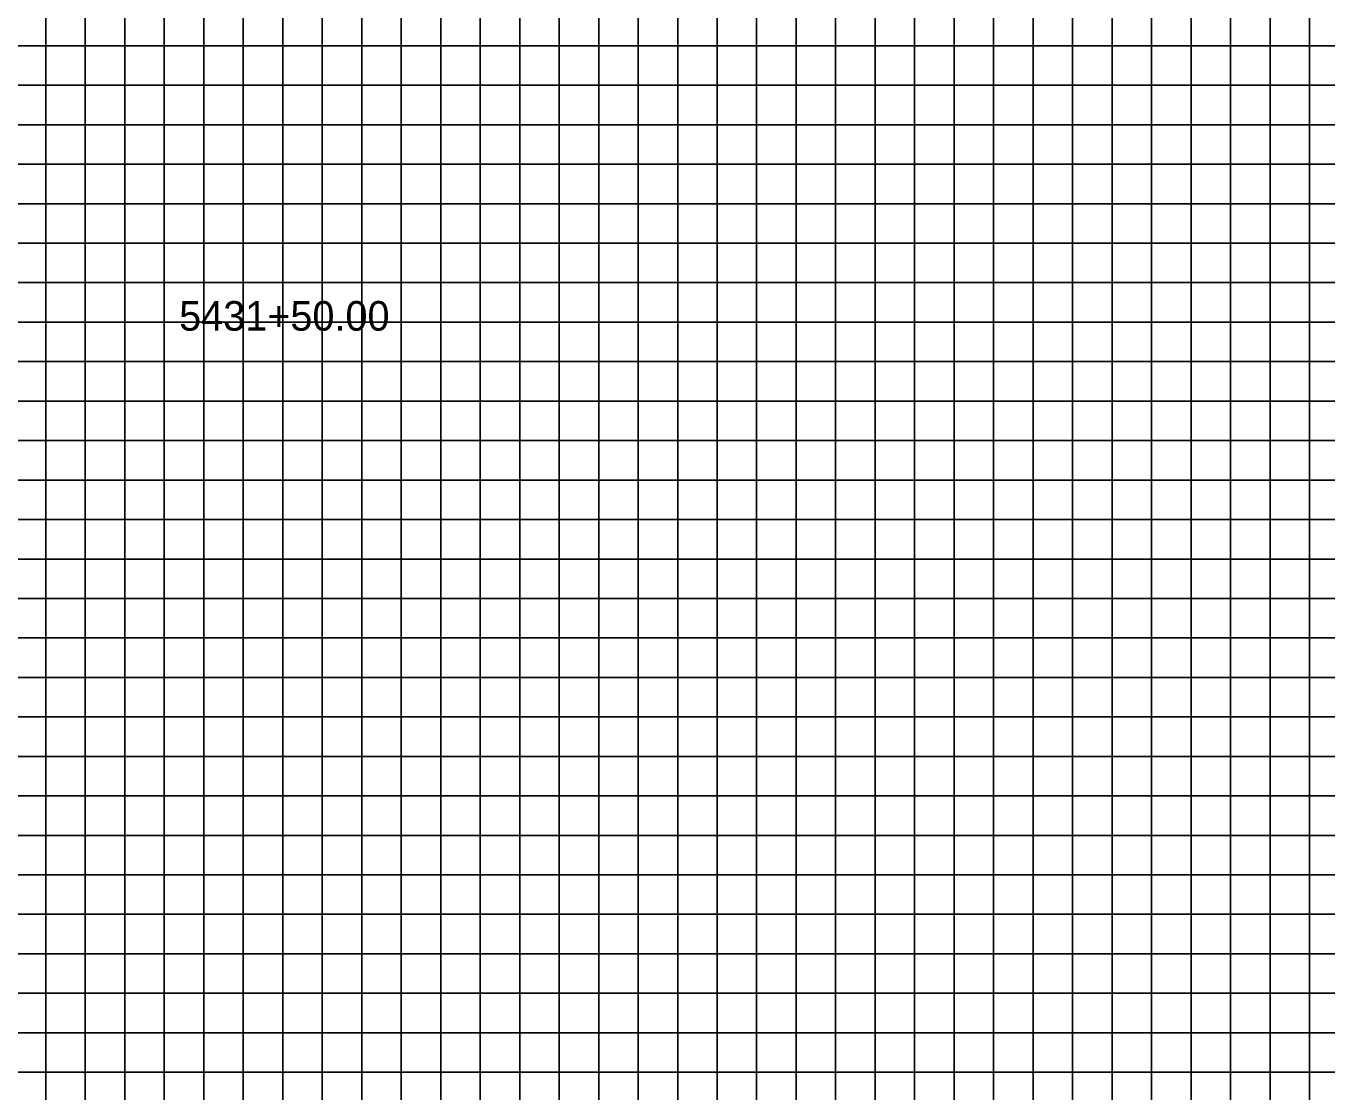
# Model space of a CAD drawing. Extents: x 967 to 1326, y 964 to 3144.
# Drawn here: x 1147 to 1212.9, y 2699 to 2753 of the extents above; entities that cross this region are included whole.
import ezdxf

# ---------------------------------------------------------------- set-up
doc = ezdxf.new("R2010")
doc.units = 0
for name, color, linetype in [('Default', 7, 'Continuous'), ('RD_GPK_XS_Cell', 7, 'Continuous'), ('RD_XS_ExGround', 7, 'Continuous')]:
    doc.layers.add(name, color=color, linetype=linetype)

msp = doc.modelspace()

# ---------------------------------------------------------------- linework, layer by layer
at = {"layer": 'RD_GPK_XS_Cell'}
for p, q in [((1150, 2680), (1150, 2850)), ((1160, 2680), (1160, 2850)), ((1170, 2680), (1170, 2850)), ((1180, 2680), (1180, 2850)), ((1190, 2680), (1190, 2850)), ((1200, 2680), (1200, 2850)), ((1210, 2680), (1210, 2850)), ((1000, 2750), (1320, 2750)), ((1000, 2740), (1320, 2740)), ((1000, 2730), (1320, 2730)), ((1000, 2720), (1320, 2720)), ((1000, 2710), (1320, 2710)), ((1000, 2700), (1320, 2700))]:
    msp.add_line(p, q, dxfattribs=at)
at = {"layer": 'RD_XS_ExGround'}
for p, q in [((1148, 2680), (1148, 2850)), ((1152, 2680), (1152, 2850)), ((1154, 2680), (1154, 2850)), ((1156, 2680), (1156, 2850)), ((1158, 2680), (1158, 2850)), ((1162, 2680), (1162, 2850)), ((1164, 2680), (1164, 2850)), ((1166, 2680), (1166, 2850)), ((1168, 2680), (1168, 2850)), ((1172, 2680), (1172, 2850)), ((1174, 2680), (1174, 2850)), ((1176, 2680), (1176, 2850)), ((1178, 2680), (1178, 2850)), ((1182, 2680), (1182, 2850)), ((1184, 2680), (1184, 2850)), ((1186, 2680), (1186, 2850)), ((1188, 2680), (1188, 2850)), ((1192, 2680), (1192, 2850)), ((1194, 2680), (1194, 2850)), ((1196, 2680), (1196, 2850)), ((1198, 2680), (1198, 2850)), ((1202, 2680), (1202, 2850)), ((1204, 2680), (1204, 2850)), ((1206, 2680), (1206, 2850)), ((1208, 2680), (1208, 2850)), ((1212, 2680), (1212, 2850)), ((1000, 2752), (1320, 2752)), ((1000, 2748), (1320, 2748)), ((1000, 2746), (1320, 2746)), ((1000, 2744), (1320, 2744)), ((1000, 2742), (1320, 2742)), ((1000, 2738), (1320, 2738)), ((1000, 2736), (1320, 2736)), ((1000, 2734), (1320, 2734)), ((1000, 2732), (1320, 2732)), ((1000, 2728), (1320, 2728)), ((1000, 2726), (1320, 2726)), ((1000, 2724), (1320, 2724)), ((1000, 2722), (1320, 2722)), ((1000, 2718), (1320, 2718)), ((1000, 2716), (1320, 2716)), ((1000, 2714), (1320, 2714)), ((1000, 2712), (1320, 2712)), ((1000, 2708), (1320, 2708)), ((1000, 2706), (1320, 2706)), ((1000, 2704), (1320, 2704)), ((1000, 2702), (1320, 2702))]:
    msp.add_line(p, q, dxfattribs=at)

# ---------------------------------------------------------------- texts
at = {"layer": 'Default'}
msp.add_text('5431+50.00', height=1.5, dxfattribs=at).set_placement((1154.755, 2737.566))

doc.saveas('drawing.dxf')
